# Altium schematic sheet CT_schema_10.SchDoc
size 278 x 170 mm
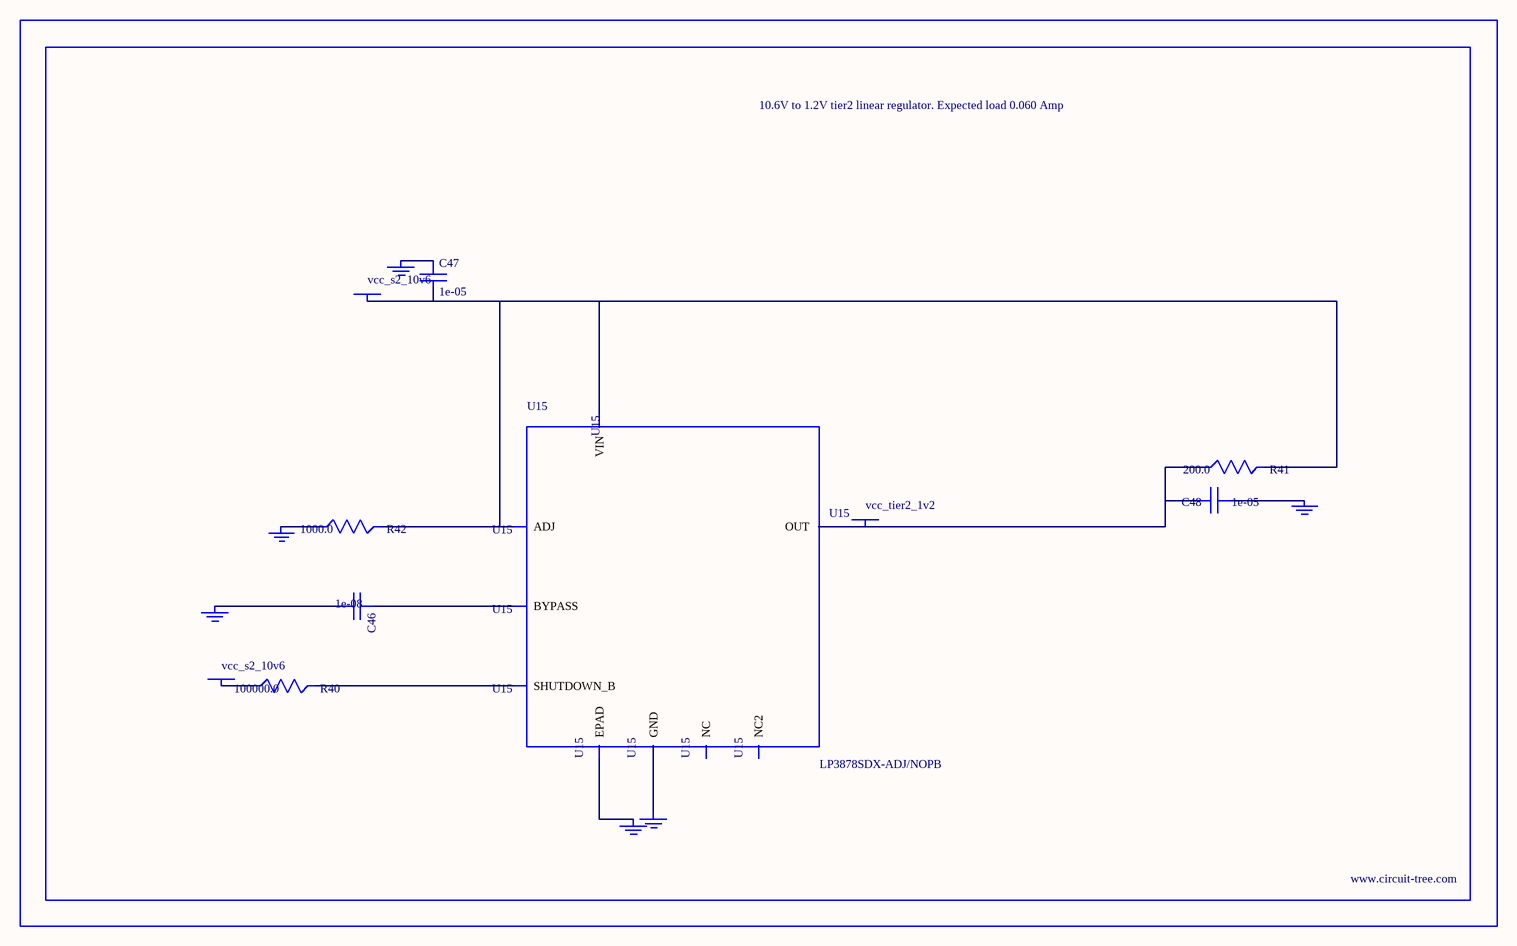
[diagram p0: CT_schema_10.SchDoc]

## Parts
BORDER9  (no value)
C46  1e-08  [C0402]
C47  1e-05  [C1206]
C48  1e-05  [C0805]
GND_INSTANCE_9_0  (no value)
GND_INSTANCE_9_1  (no value)
GND_INSTANCE_9_2  (no value)
GND_INSTANCE_9_3  (no value)
GND_INSTANCE_9_4  (no value)
GND_INSTANCE_9_5  (no value)
POWER_INSTANCE_9_0  vcc_s2_10v6
POWER_INSTANCE_9_1  vcc_s2_10v6
POWER_INSTANCE_9_2  vcc_tier2_1v2
R40  100000.0  [R0603]
R41  200.0  [R0603]
R42  1000.0  [R0603]
U15  LP3878SDX-ADJ/NOPB  [WSON-8]

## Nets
NetC46_1: C46.1 U15.1(BYPASS)
NetC46_2: C46.2 GND_INSTANCE_9_0.0(GND)
NetC47_1: C47.1 GND_INSTANCE_9_1.0(GND)
NetC47_2: C47.2 POWER_INSTANCE_9_0.0(PWR) R41.2 R42.2 U15.4(VIN) U15.6(ADJ)
NetC48_1: C48.1 GND_INSTANCE_9_2.0(GND)
NetC48_2: C48.2 POWER_INSTANCE_9_2.0(PWR) R41.1 U15.5(OUT)
NetGND_INSTANCE_9_3_0: GND_INSTANCE_9_3.0(GND) R42.1
NetGND_INSTANCE_9_4_0: GND_INSTANCE_9_4.0(GND) U15.PAD(EPAD)
NetGND_INSTANCE_9_5_0: GND_INSTANCE_9_5.0(GND) U15.3(GND)
NetPOWER_INSTANCE_9_1_0: POWER_INSTANCE_9_1.0(PWR) R40.1
NetR40_2: R40.2 U15.8(SHUTDOWN_B)

Not connected (* = marked no-connect by the designer): U15 2(NC) 7(NC2)

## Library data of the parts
BORDER9 = BORDER_PAGE9
C46 = C0402C103K3RAC
C47 = C1206C106K3RACTU
C48 = GRM219R60J106ME19D
GND_INSTANCE_9_0-GND_INSTANCE_9_5 = GND
POWER_INSTANCE_9_0-POWER_INSTANCE_9_2 = PWR
R40 = RC0603JR-07100KL
R41 = RC0603JR-07200RL
R42 = RC0603JR-071KL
